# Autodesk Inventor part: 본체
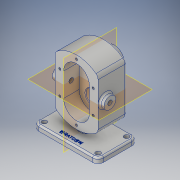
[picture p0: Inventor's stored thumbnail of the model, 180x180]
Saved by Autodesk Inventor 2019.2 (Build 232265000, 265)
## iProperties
Created: 2019-03
Part Number: 본체
Material: 알루미늄 6061
Document SubType Name: Modeling
Designer: User
Density: 2.7 g/cm^3
Appearance: 알루미늄 - 평지
Mass: 1189.14 g
Surface Area: 719.935 cm^2
Volume: 440.421 cm^3
Author: User
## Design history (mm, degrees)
sketch "스케치4"
  geometry: L1 (0, 87.6)-(0, -105.6) reference; L2 (-84, 0)-(84, 0) reference; L3 (40, 44.721)-(40, -44.721); L4 (-40, 44.721)-(-40, -44.721); A1 r 60 centre (0, 0) between (-40, -44.721) and (40, -44.721); A2 r 60 centre (0, 0) between (40, 44.721) and (-40, 44.721); 2 further points
  constraints: 4 end point, 4 point on circle, 2 centre point, 1 symmetric about line, 1 vertical
  dimensions: "d30" = 0 distance from line of L1 A1.centre; "d31" = 0 distance from line of L2 A1.centre; "d33" = 40 distance between parallel lines of L1 L4; "d34" = 80 distance between parallel lines of L3 L4; "d35" = 60 radius of A2; "d36" = 60 radius of A1
extrude "돌출1" new body sketch "스케치4" distance "d22" = 53; taper "d23" = 0 deg
sketch "스케치5"
  geometry: L1 (-60, -68)-(60, -68); L2 (60, -68)-(60, -78); L3 (60, -78)-(-60, -78); L4 (-60, -78)-(-60, -68); L5 (0, 87.6)-(0, -105.6) reference; L6 (-84, 0)-(84, 0) reference; 1 further point
  constraints: 8 end point, 2 parallel, 1 horizontal, 1 perpendicular
  dimensions: "d24" = 10 distance of L1.end L2.end; "d25" = 120 distance of L2.end L3.end; "d26" = 60 distance between parallel lines of L5 L2; "d27" = 78 distance between parallel lines of L6 L3
extrude "돌출2" join sketch "스케치5" distance "d37" = 20; taper "d39" = 0 deg; dims "d38" = 53, "d40" = 0
sketch "스케치6"
  geometry: L1 (0, -105.6)-(0, 87.6) reference; L2 (-84, 0)-(84, 0) reference; C1 r 19 at (0, 22); 1 further point
  constraints: 1 centre point
  dimensions: "d41" = 0 distance from line of L1 C1.centre; "d42" = 22 distance from line of L2 C1.centre; "d125" = 38 diameter of C1
extrude "돌출3" join sketch "스케치6" distance "d43" = 17; taper "d44" = 0 deg
sketch "스케치7"
  geometry: L1 (-38, 44.721)-(88, 44.721) reference; L2 (-20, -33.279)-(-20, -23.279) reference; L3 (0, 0)-(0, 89.443) reference; C1 r 11 at (14, 44.721); 1 further point
  constraints: 1 centre point
  dimensions: "d45" = 0 distance from line of L1 C1.centre; "d46" = 22 diameter of C1; "d124" = 14 distance from line of C1.centre L3
extrude "돌출4" join sketch "스케치7" distance "d48" = 8; taper "d49" = 0 deg
sketch "스케치8"
  geometry: L1 (-68, -53)-(-68, 20) reference; L2 (-68, -10)-(-55.776, -10); L3 (-55.776, -10)-(-55.776, -53); L4 (-55.776, -53)-(-68, -53); L5 (-68, -53)-(-68, -10); L6 (-105.6, 0)-(87.6, 0) reference; 1 further point
  constraints: 8 end point, 2 parallel, 1 horizontal, 1 perpendicular, 1 point on line
  dimensions: "d50" = 43 distance of L2.end L3.end; "d51" = 12.2244 distance of L3.end L4.end; "d52" = 10 distance between parallel lines of L6 L2
extrude "돌출5" join sketch "스케치8" stored distance "d53" = 12; taper "d54" = 0 deg
sketch "스케치9"
  geometry: L1 (0, 87.6)-(0, -105.6) reference; L2 (-84, 0)-(84, 0) reference; L3 (24, 22)-(24, -22); L4 (-24, 22)-(-24, -22); A1 r 24 centre (0, 22) between (24, 22) and (-24, 22); A2 r 24 centre (0, -22) between (-24, -22) and (24, -22); 1 further point
  constraints: 4 end point, 4 point on circle, 2 centre point, 2 tangent, 2 vertical
  dimensions: "d55" = 48 diameter of A1; "d56" = 48 diameter of A2; "d57" = 0 distance from line of L1 A1.centre; "d58" = 0 distance from line of L1 A2.centre; "d59" = 22 distance from line of L2 A1.centre; "d60" = 44 distance of A1.centre A2.centre
extrude "돌출6" cut sketch "스케치9" distance "d61" = 29; taper "d62" = 0 deg
sketch "스케치10"
  geometry: L1 (0, 87.6)-(0, -105.6) reference; L2 (-84, 0)-(84, 0) reference; C1 r 12.5 at (0, 22); C2 r 12.5 at (0, -22); 1 further point
  constraints: 2 centre point
  dimensions: "d63" = 25 diameter of C2; "d64" = 25 diameter of C1; "d65" = 0 distance from line of L1 C1.centre; "d66" = 0 distance from line of L1 C2.centre; "d67" = 44 distance of C1.centre C2.centre; "d68" = 22 distance from line of L2 C1.centre
extrude "돌출7" cut sketch "스케치10" distance "d69" = 15; taper "d70" = 0 deg
sketch "스케치11"
  geometry: C1 r 19 at (0, 0) reference; 2 further points
  constraints: 1 coincident
hole "구멍1" sketch "스케치11" at (0, 0) diameter "d71" = 17; stored, may be unused: countersink angle "d75" = 90 deg, drill point angle "d77" = 0 deg; dims "d72" = 8, "d73" = 28, "d74" = 7.3, "d76" = 30
sketch "스케치12"
  geometry: C1 r 11 at (0, 0) reference; 2 further points
  constraints: 1 coincident
hole "구멍2" sketch "스케치12" at (0, 0) diameter "d78" = 8.376; stored, may be unused: countersink angle "d82" = 90 deg, drill point angle "d84" = 118 deg; dims "d79" = 200, "d80" = 28, "d81" = 7.3, "d83" = 27.3
fillet "모깎기1" dims "d85" = 10
sketch "스케치13"
  geometry: L1 (-84, 0)-(84, 0) reference; C1 r 12.5 at (0, 22) reference; A1 r 31 centre (0, 22) between (-31, 22) and (31, 22); 2 further points
  constraints: 2 point on circle, 1 centre point, 1 coincident
  dimensions: "d93" = 62 diameter of A1; "d94" = 0 horizontal distance of A1.centre point (0, 53); "d95" = 31 distance of A1.centre point (0, 53); "d96" = 22 distance from line of L1 A1.end; "d97" = 22 distance from line of L1 A1.start
hole "구멍3" sketch "스케치13" at (0, 53), (31, 22), (-31, 22) diameter "d86" = 4.134; stored, may be unused: countersink angle "d90" = 90 deg, drill point angle "d92" = 118 deg; dims "d87" = 10, "d88" = 28, "d89" = 7.3, "d91" = 12
sketch "스케치15"
  geometry: A1 r 10 centre (-44, -20) between (-54, -20) and (-44, -30) reference; A2 r 10 centre (56, -20) between (56, -30) and (66, -20) reference; A3 r 10 centre (56, 33) between (66, 33) and (56, 43) reference; A4 r 10 centre (-44, 33) between (-44, 43) and (-54, 33) reference; 5 further points
  constraints: 4 coincident
hole "구멍4" sketch "스케치15" at (-44, -20), (56, -20), (56, 33), (-44, 33) diameter "d98" = 9; stored, may be unused: countersink angle "d102" = 90 deg, drill point angle "d104" = 118 deg; dims "d99" = 10, "d100" = 28, "d101" = 7.3, "d103" = 12
fillet "모깎기2" dims "d105" = 3
fillet "모깎기3" dims "d106" = 3
fillet "모깎기4" dims "d107" = 10
fillet "모깎기5" dims "d108" = 3
fillet "모깎기7" dims "d110" = 3
chamfer "모따기1" distance "d113" = 1; stored, may be unused: second distance "d114" = 2, angle "d115" = 45 deg
fillet "모깎기10" dims "d116" = 0.5
chamfer "모따기2" distance "d117" = 0.7; stored, may be unused: second distance "d118" = 2, angle "d119" = 30 deg
sketch "스케치17"
  geometry: L1 (53, -27)-(-47, -27) reference; L2 (-57, 36)-(-57, -17) reference; 2 further points
  constraints: 1 other
  dimensions: "d128" = 10 distance from line of L1 point (3, -17); "d129" = 60 distance from line of point (3, -17) L2
feature "엠보싱1" sketch "스케치17" dims "d122" = 0.5, "d123" = 0
fillet "모깎기11" dims "d126" = 3
fillet "모깎기12" dims "d127" = 3
node "솔리드1"
mirror "미러1"
mirror "미러2"
